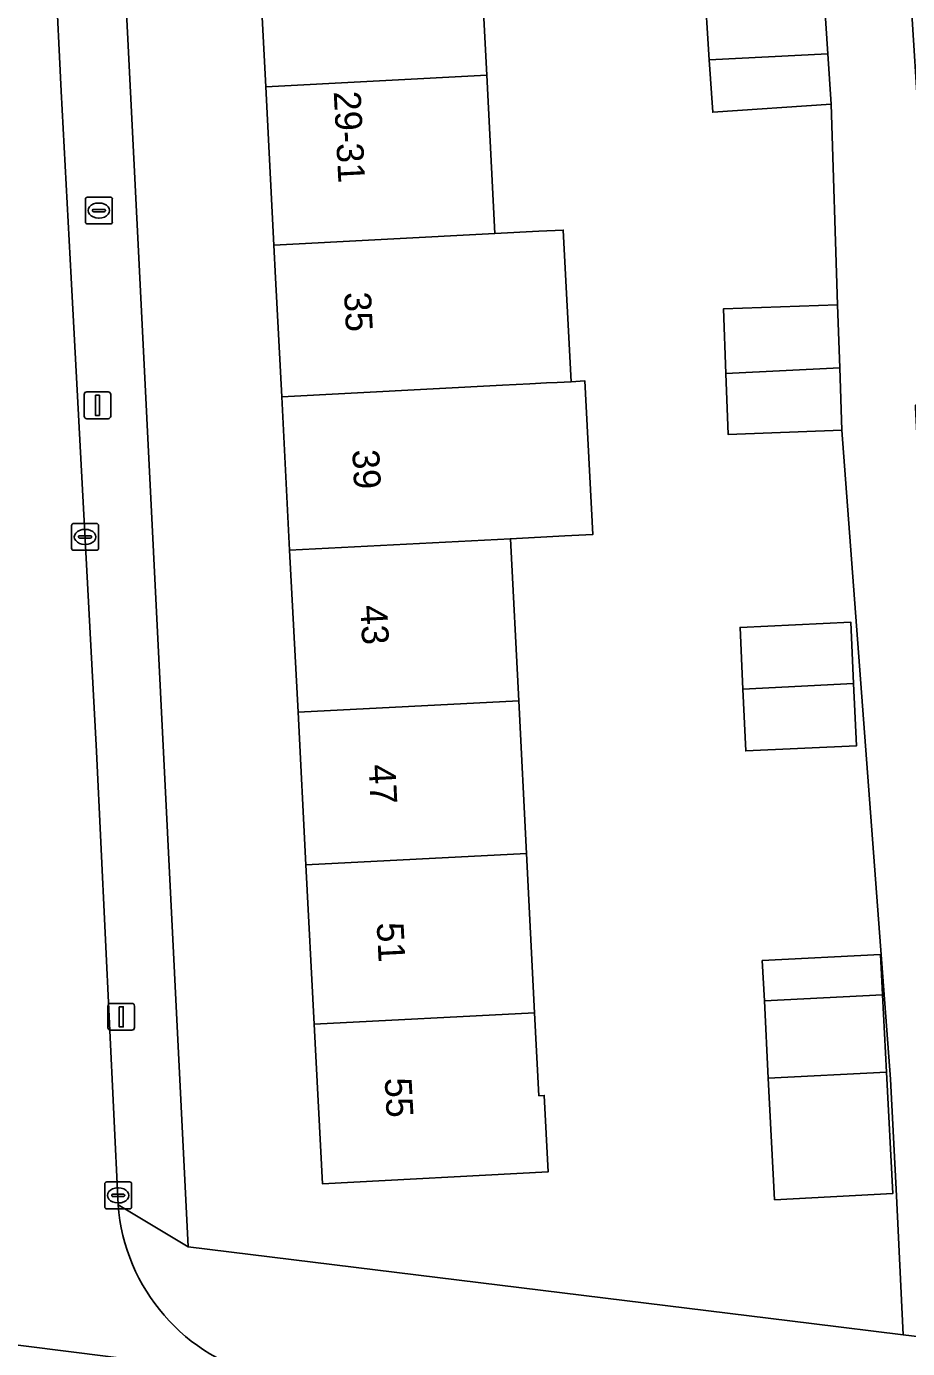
# Model space of a CAD drawing. Extents: x 158086 to 159499, y 382904 to 383981.
# Drawn here: x 158534.18 to 158567, y 383460.14 to 383509.37 of the extents above; entities that cross this region are included whole.
import ezdxf

# ---------------------------------------------------------------- set-up
doc = ezdxf.new("R2010")
doc.units = 0
for name, color, linetype in [('IMGEO_Brandkraan', 7, 'Continuous'), ('IMGEO_Erf', 7, 'Continuous'), ('IMGEO_Kolk', 7, 'Continuous'), ('IMGEO_Lichtmast', 7, 'Continuous'), ('IMGEO_Muur', 7, 'Continuous'), ('IMGEO_Pand', 7, 'Continuous'), ('IMGEO_Pand_nummerreeks', 7, 'Continuous'), ('IMGEO_Rijbaan_lokaal_open', 7, 'Continuous'), ('IMGEO_Voetpad_open', 7, 'Continuous')]:
    doc.layers.add(name, color=color, linetype=linetype)

msp = doc.modelspace()

# ---------------------------------------------------------------- linework, layer by layer
at = {"layer": 'IMGEO_Brandkraan'}
for p, q in [((158536.378, 383502.086), (158536.378, 383502.938)), ((158536.453, 383503.012), (158537.305, 383503.012)), ((158536.866, 383502.792), (158536.891, 383502.792)), ((158537.379, 383502.938), (158537.379, 383502.086)), ((158536.637, 383502.506), (158536.637, 383502.518)), ((158537.075, 383502.469), (158536.677, 383502.469)), ((158536.68, 383502.555), (158537.078, 383502.555)), ((158537.121, 383502.518), (158537.121, 383502.506)), ((158537.305, 383502.012), (158536.453, 383502.012)), ((158536.889, 383502.232), (158536.864, 383502.232))]:
    msp.add_line(p, q, dxfattribs=at)
for points in [[(158536.378, 383502.086), (158536.378, 383502.938)], [(158536.453, 383503.012), (158537.305, 383503.012)], [(158537.379, 383502.938), (158537.379, 383502.086)], [(158537.305, 383502.012), (158536.453, 383502.012)]]:
    msp.add_lwpolyline(points, dxfattribs=at)
for centre, radius, start, end in [((158536.455, 383502.936), 0.0765, 91.552, 178.448), ((158536.455, 383502.936), 0.0765, 91.552, 178.448), ((158537.303, 383502.936), 0.0765, 1.552, 88.448), ((158537.303, 383502.936), 0.0765, 1.552, 88.448), ((158536.677, 383502.515), 0.0403, 85.8775, 175.7526), ((158536.674, 383502.505), 0.0366, 178.938, 274.7102), ((158537.078, 383502.512), 0.043, 264.8664, 352.4533), ((158537.082, 383502.517), 0.0386, 1.7309, 96.639), ((158536.455, 383502.088), 0.0765, 181.552, 268.448), ((158536.455, 383502.088), 0.0765, 181.552, 268.448), ((158537.303, 383502.088), 0.0765, 271.552, 358.448), ((158537.303, 383502.088), 0.0765, 271.552, 358.448)]:
    msp.add_arc(centre, radius, start, end, dxfattribs=at)
for centre, major_axis, ratio, start_param, end_param in [((158536.865, 383502.512), (-0.387, 0.002), 0.722429, 4.712389, 7.853982), ((158536.89, 383502.512), (-0.39, 0.002), 0.717154, 1.570796, 4.712389)]:
    msp.add_ellipse(centre, major_axis=major_axis, ratio=ratio, start_param=start_param, end_param=end_param, dxfattribs=at)
at = {"layer": 'IMGEO_Erf'}
for points in [[(158536.581, 383536.306), (158538.399, 383500), (158540.205, 383463.929), (158563.419, 383461.079), (158566.843, 383460.658), (158566.587, 383465.83), (158566.372, 383470.176), (158564.559, 383494.33), (158560.32, 383494.177), (158560.239, 383496.438), (158560.152, 383498.852), (158564.391, 383499.004), (158564.162, 383506.467), (158559.749, 383506.173), (158559.619, 383508.123), (158559.421, 383511.084)], [(158551.037, 383513.215), (158551.327, 383507.548), (158551.628, 383501.654), (158553.268, 383501.739), (158554.176, 383501.786), (158554.466, 383496.139), (158554.985, 383496.166), (158555.278, 383490.448), (158554.239, 383490.394), (158552.21, 383490.289), (158552.518, 383484.261), (158552.809, 383478.571), (158553.112, 383472.642), (158553.27, 383469.554), (158553.469, 383469.563), (158553.611, 383466.716), (158545.204, 383466.28), (158544.897, 383472.217), (158544.591, 383478.146), (158544.297, 383483.835), (158543.985, 383489.864), (158543.689, 383495.581), (158543.461, 383500), (158543.398, 383501.228), (158543.093, 383507.122), (158542.8, 383512.789)]]:
    msp.add_lwpolyline(points, dxfattribs=at)
for points in [[(158560.87, 383484.694), (158560.765, 383486.992), (158564.891, 383487.181), (158564.995, 383484.908), (158565.102, 383482.582), (158560.976, 383482.393)], [(158566.075, 383473.313), (158566.223, 383470.431), (158566.454, 383465.91), (158562.047, 383465.684), (158561.815, 383470.205), (158561.668, 383473.085), (158561.591, 383474.585), (158565.998, 383474.81)]]:
    msp.add_lwpolyline(points, close=True, dxfattribs=at)
at = {"layer": 'IMGEO_Kolk'}
for p, q in [((158535.863, 383489.935), (158535.863, 383490.787)), ((158535.938, 383490.861), (158536.79, 383490.861)), ((158536.351, 383490.641), (158536.376, 383490.641)), ((158536.864, 383490.787), (158536.864, 383489.935)), ((158536.122, 383490.355), (158536.122, 383490.367)), ((158536.56, 383490.318), (158536.162, 383490.318)), ((158536.165, 383490.404), (158536.563, 383490.404)), ((158536.374, 383490.081), (158536.349, 383490.081)), ((158536.606, 383490.367), (158536.606, 383490.355)), ((158536.79, 383489.861), (158535.938, 383489.861)), ((158537.172, 383466.343), (158538.024, 383466.343)), ((158537.097, 383465.417), (158537.097, 383466.269)), ((158537.356, 383465.837), (158537.356, 383465.849)), ((158537.399, 383465.886), (158537.797, 383465.886)), ((158537.585, 383466.123), (158537.61, 383466.123)), ((158537.84, 383465.849), (158537.84, 383465.837)), ((158538.098, 383466.269), (158538.098, 383465.417)), ((158537.794, 383465.8), (158537.396, 383465.8)), ((158537.608, 383465.563), (158537.583, 383465.563)), ((158538.024, 383465.343), (158537.172, 383465.343))]:
    msp.add_line(p, q, dxfattribs=at)
for points in [[(158535.863, 383489.935), (158535.863, 383490.787)], [(158535.938, 383490.861), (158536.79, 383490.861)], [(158536.864, 383490.787), (158536.864, 383489.935)], [(158536.79, 383489.861), (158535.938, 383489.861)], [(158537.172, 383466.343), (158538.024, 383466.343)], [(158537.097, 383465.417), (158537.097, 383466.269)], [(158538.098, 383466.269), (158538.098, 383465.417)], [(158538.024, 383465.343), (158537.172, 383465.343)]]:
    msp.add_lwpolyline(points, dxfattribs=at)
for centre, radius, start, end in [((158535.94, 383490.785), 0.0765, 91.552, 178.448), ((158535.94, 383490.785), 0.0765, 91.552, 178.448), ((158536.788, 383490.785), 0.0765, 1.552, 88.448), ((158536.788, 383490.785), 0.0765, 1.552, 88.448), ((158536.162, 383490.364), 0.0403, 85.8775, 175.7526), ((158536.159, 383490.354), 0.0366, 178.938, 274.7102), ((158536.563, 383490.361), 0.043, 264.8664, 352.4533), ((158536.567, 383490.366), 0.0386, 1.7309, 96.639), ((158535.94, 383489.937), 0.0765, 181.552, 268.448), ((158535.94, 383489.937), 0.0765, 181.552, 268.448), ((158536.788, 383489.937), 0.0765, 271.552, 358.448), ((158536.788, 383489.937), 0.0765, 271.552, 358.448), ((158537.174, 383466.267), 0.0765, 91.552, 178.448), ((158537.174, 383466.267), 0.0765, 91.552, 178.448), ((158538.022, 383466.267), 0.0765, 1.552, 88.448), ((158538.022, 383466.267), 0.0765, 1.552, 88.448), ((158537.396, 383465.846), 0.0403, 85.8775, 175.7526), ((158537.801, 383465.848), 0.0386, 1.7309, 96.639), ((158537.174, 383465.419), 0.0765, 181.552, 268.448), ((158537.174, 383465.419), 0.0765, 181.552, 268.448), ((158537.393, 383465.836), 0.0366, 178.938, 274.7102), ((158537.797, 383465.843), 0.043, 264.8664, 352.4533), ((158538.022, 383465.419), 0.0765, 271.552, 358.448), ((158538.022, 383465.419), 0.0765, 271.552, 358.448)]:
    msp.add_arc(centre, radius, start, end, dxfattribs=at)
for centre, major_axis, ratio, start_param, end_param in [((158536.35, 383490.361), (-0.387, 0.002), 0.722429, 4.712389, 7.853982), ((158536.375, 383490.361), (-0.39, 0.002), 0.717154, 1.570796, 4.712389), ((158537.584, 383465.843), (-0.387, 0.002), 0.722429, 4.712389, 7.853982), ((158537.609, 383465.843), (-0.39, 0.002), 0.717154, 1.570796, 4.712389)]:
    msp.add_ellipse(centre, major_axis=major_axis, ratio=ratio, start_param=start_param, end_param=end_param, dxfattribs=at)
at = {"layer": 'IMGEO_Lichtmast'}
for p, q in [((158536.33, 383494.86), (158536.33, 383495.66)), ((158536.33, 383495.66), (158536.33, 383494.86)), ((158536.43, 383495.76), (158537.22, 383495.76)), ((158537.22, 383495.76), (158536.43, 383495.76)), ((158537.32, 383495.66), (158537.32, 383494.86)), ((158537.32, 383494.86), (158537.32, 383495.66)), ((158537.22, 383494.76), (158536.43, 383494.76)), ((158536.43, 383494.76), (158537.22, 383494.76)), ((158537.214, 383472.094), (158537.214, 383472.894)), ((158537.214, 383472.894), (158537.214, 383472.094)), ((158537.314, 383472.994), (158538.104, 383472.994)), ((158538.104, 383472.994), (158537.314, 383472.994)), ((158538.204, 383472.894), (158538.204, 383472.094)), ((158538.204, 383472.094), (158538.204, 383472.894)), ((158538.104, 383471.994), (158537.314, 383471.994)), ((158537.314, 383471.994), (158538.104, 383471.994))]:
    msp.add_line(p, q, dxfattribs=at)
for points in [[(158536.75, 383495.635), (158536.9, 383495.635), (158536.9, 383494.885), (158536.75, 383494.885), (158536.75, 383495.635)], [(158537.634, 383472.869), (158537.784, 383472.869), (158537.784, 383472.119), (158537.634, 383472.119), (158537.634, 383472.869)]]:
    msp.add_lwpolyline(points, dxfattribs=at)
for centre, start, end in [((158536.43, 383495.66), 90, 180), ((158536.43, 383495.66), 90, 180), ((158537.22, 383495.66), 0, 90), ((158537.22, 383495.66), 360, 90), ((158536.43, 383494.86), 180, 270), ((158536.43, 383494.86), 180, 270), ((158537.22, 383494.86), 270, 0), ((158537.22, 383494.86), 270, 0), ((158537.314, 383472.894), 90, 180), ((158537.314, 383472.894), 90, 180), ((158538.104, 383472.894), 0, 90), ((158538.104, 383472.894), 360, 90), ((158537.314, 383472.094), 180, 270), ((158537.314, 383472.094), 180, 270), ((158538.104, 383472.094), 270, 0), ((158538.104, 383472.094), 270, 0)]:
    msp.add_arc(centre, 0.1, start, end, dxfattribs=at)
at = {"layer": 'IMGEO_Muur'}
msp.add_lwpolyline([(158563.419, 383461.079), (158540.205, 383463.929)], dxfattribs=at)
at = {"layer": 'IMGEO_Pand'}
for points in [[(158543.093, 383507.122), (158551.327, 383507.548), (158551.037, 383513.215), (158542.8, 383512.789)], [(158564.036, 383508.349), (158563.834, 383511.378), (158559.421, 383511.084), (158559.619, 383508.123)], [(158564.036, 383508.349), (158559.619, 383508.123), (158559.749, 383506.173), (158564.162, 383506.467)], [(158543.093, 383507.122), (158543.398, 383501.228), (158551.628, 383501.654), (158551.327, 383507.548)], [(158551.628, 383501.654), (158543.398, 383501.228), (158543.461, 383500), (158543.689, 383495.581), (158551.917, 383496.007), (158552.932, 383496.06), (158553.557, 383496.092), (158553.946, 383496.112), (158554.466, 383496.139), (158554.176, 383501.786), (158553.268, 383501.739)], [(158564.475, 383496.657), (158564.391, 383499.004), (158560.152, 383498.852), (158560.239, 383496.438)], [(158564.475, 383496.657), (158560.239, 383496.438), (158560.32, 383494.177), (158564.559, 383494.33)], [(158554.466, 383496.139), (158553.946, 383496.112), (158553.557, 383496.092), (158552.932, 383496.06), (158551.917, 383496.007), (158543.689, 383495.581), (158543.985, 383489.864), (158552.21, 383490.289), (158554.239, 383490.394), (158555.278, 383490.448), (158554.985, 383496.166)], [(158544.297, 383483.835), (158552.518, 383484.261), (158552.21, 383490.289), (158543.985, 383489.864)], [(158560.87, 383484.694), (158564.995, 383484.908), (158564.891, 383487.181), (158560.765, 383486.992)], [(158560.87, 383484.694), (158560.976, 383482.393), (158565.102, 383482.582), (158564.995, 383484.908)], [(158544.297, 383483.835), (158544.591, 383478.146), (158552.809, 383478.571), (158552.518, 383484.261)], [(158544.897, 383472.217), (158553.112, 383472.642), (158552.809, 383478.571), (158544.591, 383478.146)], [(158561.668, 383473.085), (158566.075, 383473.313), (158565.998, 383474.81), (158561.591, 383474.585)], [(158566.075, 383473.313), (158561.668, 383473.085), (158561.815, 383470.205), (158566.223, 383470.431)], [(158544.897, 383472.217), (158545.204, 383466.28), (158553.611, 383466.716), (158553.469, 383469.563), (158553.27, 383469.554), (158553.112, 383472.642)], [(158566.223, 383470.431), (158561.815, 383470.205), (158562.047, 383465.684), (158566.454, 383465.91)]]:
    msp.add_lwpolyline(points, close=True, dxfattribs=at)
at = {"layer": 'IMGEO_Rijbaan_lokaal_open'}
for points in [[(158536.793, 383482.371), (158535.844, 383500), (158535.469, 383506.96), (158534.418, 383528.681)], [(158537.594, 383465.494), (158536.793, 383482.371)], [(158543.141, 383459.099), (158528.241, 383460.972), (158525.94, 383461.229), (158520.471, 383461.894), (158500.312, 383464.317), (158496.641, 383464.765), (158489.019, 383465.699), (158477.274, 383467.199), (158473.136, 383467.758), (158471.246, 383468.043), (158470.237, 383461.129), (158472.01, 383460.949), (158472.205, 383460.918), (158476.869, 383460.346), (158492.123, 383458.465)], [(158528.241, 383460.972), (158543.141, 383459.099)]]:
    msp.add_lwpolyline(points, dxfattribs=at)
msp.add_arc((158544.672, 383466.03), 7.099, 184.3337, 257.5428, dxfattribs=at)
at = {"layer": 'IMGEO_Voetpad_open'}
for points in [[(158534.418, 383528.681), (158535.469, 383506.96), (158535.844, 383500), (158536.793, 383482.371), (158537.594, 383465.494), (158540.205, 383463.929), (158538.399, 383500), (158536.581, 383536.306), (158536.527, 383537.377), (158536.486, 383538.199), (158536.228, 383538.739), (158535.582, 383540.092), (158527.266, 383557.496)], [(158563.834, 383511.378), (158564.036, 383508.349), (158564.162, 383506.467), (158564.391, 383499.004), (158564.475, 383496.657), (158564.559, 383494.33), (158566.372, 383470.176), (158566.587, 383465.83), (158566.843, 383460.658), (158569.101, 383460.381), (158567.299, 383495.181), (158567.295, 383495.26), (158567.9, 383495.297), (158567.756, 383498.381), (158567.634, 383501.01), (158567.519, 383503.481), (158567.396, 383506.11), (158567.165, 383509.84)], [(158568.943, 383459.053), (158569.101, 383460.381), (158566.843, 383460.658), (158563.419, 383461.079), (158540.205, 383463.929), (158537.594, 383465.494)]]:
    msp.add_lwpolyline(points, dxfattribs=at)
msp.add_arc((158544.672, 383466.03), 7.099, 184.3337, 257.5428, dxfattribs=at)

# ---------------------------------------------------------------- texts
at = {"layer": 'IMGEO_Pand_nummerreeks'}
for s, rotation, p in [('29-31', 272.9623, (158545.626, 383506.937)), ('35', 272.962, (158546.012, 383499.46)), ('39', 272.962, (158546.316, 383493.597)), ('43', 272.9624, (158546.615, 383487.805)), ('47', 272.9525, (158546.922, 383481.871)), ('51', 272.9562, (158547.226, 383475.987)), ('55', 272.959, (158547.525, 383470.204))]:
    msp.add_text(s, height=1, rotation=rotation, dxfattribs=at).set_placement(p)

doc.saveas('drawing.dxf')
